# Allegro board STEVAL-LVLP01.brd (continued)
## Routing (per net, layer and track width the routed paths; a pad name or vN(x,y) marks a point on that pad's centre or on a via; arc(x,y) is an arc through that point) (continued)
N470361: length 8.5
  TOP w0.305: U4.4 41.87,75.76 C31.2 41.87,78.86 R81.1 TP14.1
N471408: length 6.7
  TOP w0.305: R76.1 40.07,66.06 41.91,66.06 42.48,66.63 R73.1 42.85,66.45 U2.10
N471412: length 4.7
  TOP w0.305: R75.1 41.27,68.03 R77.1 43.98,67.1 U2.9
N471570: length 4
  TOP w0.305: R74.2 R77.2 44.72,67.75 U2.8
N472042: length 6.6
  TOP w0.305: R81.2 v1(40.45,79.77)
  BOTTOM w0.305: J4.2 37.53,82.69 v1(40.45,79.77)
N472582: length 4.9
  TOP w0.381: R66.1 R57.2 43.31,88.79 41.08,86.57 R58.2
N478538: length 9.1
  TOP w0.305: R101.2 80.39,12.15 80.39,10.11 R96.1 79.63,8.4 J6.1
N478542: length 9.4
  TOP w0.305: R102.2 82.17,12.15 82.17,10.11 R97.1 81.41,9.16 J6.2
N478546: length 10.1
  TOP w0.305: J6.3 83.76,9.35 R98.1 83.95,10.11 83.95,12.15 R104.2
N478738: length 10.5
  TOP w0.508: J5.2 90.04,10.35 90.46,9.93 C42.1 90.46,8.13 90.04,7.72 J6.4
N479415: length 17.1
  TOP w0.254: R106.2 v1(50.45,13)
  BOTTOM w0.254: J9.1 41.34,13.67 49.78,13.67 v1(50.45,13)
N479421: length 13.8
  TOP w0.254: J9.2 43.43,14.11 51.12,14.11 R107.2
N479427: length 10.5
  TOP w0.254: R108.2 52.45,14.56 45.53,14.56 J9.3
N479459: length 32.2
  TOP w0.508: J9.4 46.86,18.65 C48.1 47.41,19.7 47.92,20.21 49.4,20.21 53.85,15.77 65.53,15.77 66.93,17.16 70.87,17.16 J8.2
N479601: length 2.3
  TOP w0.305: R114.2 39.24,5.61
N479607: length 2.3
  TOP w0.305: R115.2 41.78,5.61
N479625: length 2.3
  TOP w0.305: J11.4 R116.2
N479657: length 30.3
  TOP w0.508: J11.5 46.86,8.49 C52.1
  TOP w0.635: J11.5 48.39,4.08 70.74,4.08 J10.2
N479733: length 2.3
  TOP w0.305: R113.2 36.7,5.61
N480096: length 5.5
  TOP w0.381: 34.97,22.71 35.04,22.65 U7.3 ; 34.97,22.71 C51.2 38.71,22.71 R111.2 ; 34.97,22.71 34.97,22.76 R110.1
N487267: length 49.6
  TOP w0.305: v1(96.39,20.46) 102.11,26.18 R28.2 ; R29.1 v1(57.09,21.73)
  BOTTOM w0.305: v1(57.09,21.73) 58.36,20.46 v1(96.39,20.46)
N487934: length 41.9
  TOP w0.305: R30.2 102.11,27.83 v1(96.39,22.12) ; R31.1 v1(65.09,21.73)
  BOTTOM w0.305: v1(96.39,22.12) 95.25,20.97 65.85,20.97 v1(65.09,21.73)
N488373: length 34
  TOP w0.305: R33.1 v1(73.09,21.73) ; R32.2 102.11,29.48 v1(96.39,23.77)
  BOTTOM w0.305: v1(96.39,23.77) 94.23,21.61 73.22,21.61 v1(73.09,21.73)
N490756: length 3.3
  TOP w0.305: C22.2 R45.1 54.93,72.6 R46.1
N494551: length 1.7
  TOP w0.305: 53.34,62.03 53.37,62.06 R72.1
N494643: length 10.4
  TOP w0.305: R68.1 58.86,65.55 57.28,65.55 56.71,64.98 R63.1 55.94,65.55 54.1,65.55 53.53,64.98 R61.2 53.16,65.15 U2.3
N494647: length 7.7
  TOP w0.305: R72.2 R70.2 ; R72.2 R67.1 ; R72.2 54.96,63.48 53.34,63.48 52.32,64.5 U2.2
N494767: length 3.4
  TOP w0.305: R65.1 54.93,58.88 R64.1 C27.2
N495845: length 1.7
  TOP w0.305: R87.1 42.65,62.06 42.67,62.03
N495931: length 10.1
  TOP w0.305: R85.1 37.02,65.55 38.73,65.55 39.31,64.98 R80.1 40.07,65.55 41.91,65.55 42.48,64.98 R78.2 42.85,65.15 U2.12
N495935: length 7.7
  TOP w0.305: R87.2 41.05,63.48 42.67,63.48 43.69,64.5 U2.13 ; R87.2 R84.1 ; R87.2 R89.2
N496035: length 3.3
  TOP w0.305: C32.2 R82.1 41.08,59.01 R83.1
N496697: length 8.5
  TOP w0.381: R51.1 51.94,88.79 50.93,89.81 R50.1 48.58,89.81 R55.2 46.67,89.87 R52.1
N501821: length 90.6
  TOP w0.508: R99.2 94.87,27.64 94.87,4.34 92.71,2.18 R100.1
N513408: length 3.4
  TOP w0.33: C8.1 59.49,35.08 U1.13
N519464: length 2
  TOP w0.508: R105.2 104.84,72.53 LED3.1
N526328: length 1.9
  TOP w0.381: R94.1 36.26,103.52 LED2.2
N526332: length 15.8
  TOP w0.381: LED2.1 44.2,103.52 50.8,96.92 Q7.3
N574651: length 6.4
  TOP w0.305: R108.1 56.07,14.11 57.91,14.11 58.38,13.64 C49.2 58.64,13.23 59.16,12.71 U6.9
N574774: length 6.2
  TOP w0.305: R107.1 56.07,12.34 57.91,12.34 58.38,11.87 C47.2 58.42,11.41 U6.11
N574847: length 6.3
  TOP w0.305: U6.14 58.6,9.46 C46.2 58.38,10.09 57.91,10.56 56.07,10.56 R106.1
N575649: length 30.8
  TOP w0.305: v1(40.01,10.69) 39.43,10.69 R112.2 R114.1 ; U6.3 64.81,9.46 62.61,7.26 54.74,7.26 52.41,9.58 52.41,10.01 v1(52.45,10.05)
  BOTTOM w0.305: v1(52.45,10.05) 52.01,10.49 40.2,10.49 v1(40.01,10.69)
N599590: length 1.4
  TOP w0.508: R34.1 C16.2
N599920: length 1.4
  TOP w0.508: R36.1 C17.2
N600140: length 1.4
  TOP w0.508: R38.1 C18.2
N605072: length 4.6
  TOP w0.381: R66.2 46.29,88.69 U3.4 42.77,86.69 C25.2
N605096: length 6.6
  TOP w0.381: U3.1 46.16,84.79 45.21,85.74 43.69,85.74 43.09,85.14 C25.1 40.92,85.14 R58.1

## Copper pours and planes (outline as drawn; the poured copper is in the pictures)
5V on TOP: 41.02,106.57 41.02,104.79 46.74,104.79 46.74,106.57
5V on TOP: 30.66,18.18 32.84,15.99 32.84,14.75 18.49,14.75 18.36,14.88 18.36,18.05 18.49,18.18 ; 1 cut-out
5V on BOTTOM: 30.81,17.67 31.19,17.29 31.19,15.13 30.81,14.75 18.49,14.75 18.36,14.88 18.36,17.54 18.49,17.67
GND on TOP: 81.15,56.02 81.15,52.98 79.12,52.98 77.72,54.37 77.72,56.02 77.85,56.15 81.03,56.15
GND on TOP: 57.28,87.39 69.34,87.39 69.47,87.27 69.47,82.31 69.85,81.93 104.65,81.93 104.78,81.81 104.78,75.2 104.52,74.95 104.52,73.68 102.87,72.03 102.87,71.14 79.38,71.14 76.45,74.06 70.74,74.06 67.69,71.01 67.69,31.26 70.23,28.72 81.03,28.72 81.15,28.59 81.15,25.16 81.03,25.04 63.75,25.04 63.12,25.67 63.12,29.61 62.36,30.37 61.09,30.37 61.09,31.89 62.36,31.89 63.37,32.91 63.12,79.27 57.15,85.23 57.15,87.27
GND on TOP: 81.15,42.31 81.15,39.26 79.12,39.26 77.72,40.66 77.72,42.31 77.85,42.44 81.03,42.44
GND on TOP: 48.51,44.47 48.51,41.04 51.18,38.37 51.18,36.97 46.74,36.97 46.61,37.1 46.61,44.34 46.74,44.47
GND on BOTTOM: 50.55,36.47 46.48,36.47 46.35,36.59 46.35,52.98 46.48,53.1 56.9,53.1 63.12,59.33 63.12,79.77 58.17,84.73 58.17,87.27 58.42,87.52 69.22,87.52 69.47,87.27 69.47,82.31 69.85,81.93 76.83,81.93 82.04,76.73 82.04,25.16 81.92,25.04 61.98,25.04 ; 2 cut-outs
GND_SIGNAL on TOP: 27.94,101.74 62.36,101.74 62.48,101.62 62.48,98.57 63.25,97.81 63.25,94.89 63.5,94.63 67.69,94.63 67.82,94.51 67.82,93.49 67.69,93.36 66.17,93.36 65.66,93.87 63.5,93.87 63.25,93.62 63.25,88.54 63.37,88.41 63.37,87.65 51.69,87.65 44.7,94.63 40.89,94.63 32.77,86.5 32.77,71.77 26.8,65.8 26.49,65.62 26.46,65.65 26.41,65.66 25.64,65.66 25.55,65.61 25.56,65.5 25.56,65.45 25.53,65.42 24.38,65.42 24.38,64.79 24.24,64.85 24.18,64.99 24.12,65.08 24.01,65.06 23.73,64.78 23.66,64.73 23.58,64.69 23.51,64.62 23.53,64.53 23.59,64.45 23.64,64.36 21.03,64.29 22.04,65.3 22.16,65.38 22.3,65.41 22.41,65.41 22.41,65.48 22.39,65.5 22.24,65.74 22.18,66.03 22.18,66.09 22.19,66.15 22.14,66.26 22.02,66.24 20.1,64.33 20.08,64.3 20.07,64.27 15.49,64.15 15.24,64.41 15.24,89.04 ; 4 cut-outs
GND_SIGNAL on TOP: 39.24,21.73 39.24,19.7 36.45,19.7 35.69,20.46 34.42,20.46 34.42,20.97 35.69,20.97 36.45,21.73
GND_SIGNAL on TOP: 38.61,76.85 38.61,72.66 40.89,72.66 40.89,76.85
GND_SIGNAL on BOTTOM: 13.21,108.35 69.22,108.35 69.47,108.09 69.47,87.9 69.22,87.65 58.29,87.65 58.04,87.39 58.04,84.47 62.99,79.52 62.99,59.33 56.9,53.23 46.48,53.23 46.23,52.98 46.23,36.47 46.35,36.34 49.4,36.34 61.72,24.02 93.98,24.02 94.23,23.77 94.23,1.03 93.98,0.78 13.21,0.78 12.95,1.03 12.95,108.09 ; 8 cut-outs
V1 on TOP (solid shape): 84.38,64.71 85.52,64.71 85.52,62.32 84.38,62.32 84.38,61.74 84.02,61.74 84.02,62.32 83.67,62.32 83.67,64.71 84.02,64.71 84.02,65.3 84.38,65.3
V1 on TOP: 83.82,70.25 83.69,70.12 83.69,58.69 90.17,58.69 96.77,52.09 103.76,52.09 104.01,52.34 104.01,61.61 103.38,62.25 103.38,64.28 102.36,64.28 102.11,64.53 102.11,69.99 101.85,70.25
V2 on TOP (solid shape): 84.38,50.99 85.52,50.99 85.52,48.61 84.38,48.61 84.38,48.02 84.02,48.02 84.02,48.61 83.67,48.61 83.67,50.99 84.02,50.99 84.02,51.58 84.38,51.58
V2 on TOP: 83.69,44.98 103.76,44.98 104.01,45.23 104.01,51.33 103.76,51.58 96.52,51.58 95.5,52.6 83.82,52.6 83.69,52.47
V3 on TOP (solid shape): 84.38,37.28 85.52,37.28 85.52,34.89 84.38,34.89 84.38,34.31 84.02,34.31 84.02,34.89 83.67,34.89 83.67,37.28 84.02,37.28 84.02,37.86 84.38,37.86
V3 on TOP: 83.82,38.88 83.69,38.75 83.69,31.26 103.76,31.26 104.01,31.51 104.01,44.21 103.76,44.47 97.03,44.47 91.44,38.88
VDD on TOP: 36.58,53.48 36.7,53.61 36.7,54.75 36.58,54.88 35.43,54.88 35.43,54.25 36.2,53.48
BUCK_OUT on TOP: 60.2,103.4 60.2,106.7 60.07,106.82 47.12,106.82 46.99,106.7 46.99,103.4 47.12,103.27 60.07,103.27
LSS1 on TOP: 71.95,66.82 71.95,63.52 76.71,63.52 77.22,63.01 83.31,63.01 83.31,66.69 83.19,66.82
LSS3 on TOP: 72.01,39.39 72.01,36.09 76.96,36.09 77.47,35.58 83.31,35.58 83.31,38.75 83.19,38.88 78.87,38.88 78.36,39.39
SHUNT1P on TOP: 71.5,73.55 76.2,73.55 76.45,73.3 76.45,67.07 68.33,67.07 68.33,68.34 71.25,71.26 71.25,73.3
SHUNT2P on TOP: 76.45,39.64 76.45,49.04 76.71,49.29 83.31,49.29 83.31,52.47 83.19,52.6 78.87,52.6 76.45,55.01 76.45,63.26 68.33,63.26 68.33,56.02 69.72,54.63 69.72,53.36 71.25,51.83 71.25,51.33 68.33,48.4 68.33,39.64
SHUNT3P on TOP: 68.33,35.83 76.45,35.83 76.45,29.61 76.2,29.35 71.5,29.35 71.25,29.61 71.25,31.64 68.33,34.56
VM on TOP (solid shape): 85.39,57.98 85.98,57.98 85.98,57.62 85.39,57.62 85.39,56.48 83.01,56.48 83.01,57.62 82.42,57.62 82.42,57.98 83.01,57.98 83.01,58.34 85.39,58.34
VM on TOP (solid shape): 85.39,44.26 85.98,44.26 85.98,43.91 85.39,43.91 85.39,42.77 83.01,42.77 83.01,43.91 82.42,43.91 82.42,44.26 83.01,44.26 83.01,44.62 85.39,44.62
VM on TOP (solid shape): 85.39,30.55 85.98,30.55 85.98,30.19 85.39,30.19 85.39,29.05 83.01,29.05 83.01,30.19 82.42,30.19 82.42,30.55 83.01,30.55 83.01,30.9 85.39,30.9
VM on TOP: 82.55,44.59 82.42,44.47 82.42,39.39 82.55,39.26 91.19,39.26 93.34,41.42 93.34,42.44 91.19,44.59
VM on TOP: 69.85,82.44 69.98,82.31 104.78,82.31 104.78,91.97 104.65,92.09 69.98,92.09 69.85,91.97
VM on TOP: 82.55,58.31 82.42,58.18 82.42,53.1 82.55,52.98 93.09,52.98 93.34,53.23 93.34,55.01 90.04,58.31
VM on TOP: 82.55,30.88 82.42,30.75 82.42,25.67 82.55,25.54 93.09,25.54 93.34,25.8 93.34,30.62 93.09,30.88
VM on BOTTOM: 82.43,24.27 82.3,76.98 76.96,82.31 69.98,82.31 69.85,82.44 69.85,91.97 69.98,92.09 104.65,92.09 104.78,91.97 104.78,82.44 104.65,82.31 100.58,82.31 96.27,78 96.27,25.8 94.74,24.27
N348034 on TOP: 53.85,69.11 52.83,69.11 51.69,67.96 51.69,67.58 50.04,67.58 50.04,70.76 50.8,71.52 53.98,71.52 53.98,69.23
N420950 on TOP: 65.41,96.54 65.53,96.66 68.58,96.66 68.71,96.79 68.71,106.19 68.58,106.32 62.99,106.32 62.87,106.19 62.87,98.32 63.5,97.68 63.5,96.54
N423156 on TOP: 63.5,93.24 63.5,88.92 63.63,88.79 69.47,88.79 69.6,88.92 69.6,92.22 68.58,93.24
N472470 on TOP: 46.35,86.38 46.35,87.14 48.13,88.92 48.9,88.92 48.9,88.28 49.91,87.27 50.67,87.27 50.67,86.25 48.13,86.25 48.01,86.38
N494551 on TOP: 50.04,64.03 51.31,64.03 52.83,62.5 53.85,62.5 53.98,62.37 53.98,60.09 51.18,60.09 50.29,60.98 50.29,62.12 50.04,62.37
N495845 on TOP: 45.97,64.03 45.97,62.37 45.09,61.49 45.09,60.34 44.83,60.09 42.04,60.09 42.04,62.5 43.18,62.5 44.7,64.03

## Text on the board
Ref Des/Silkscreen Top: VBUS | nFAULT | REG12 | VM | CP | OPREF | GND | TPCB | 5V | I3 | I1 | CREF | I2 | PG | PH_1 | CFBK | PH_2 | PH_3 | CURR | REF IN | nSS | A | MISO | B | MOSI | Z | SCLK | SCREF | VEnc | VSPI | 3.3V | H1 | H2 | H3 | VHall | 3sh | 1sh | V1 | V2 | V3 | FOR EVALUATION ONLY | NOT FCC APPROVED FOR RESALE | 6V-45V | STEVAL$LVLP01A | + | - | STEVAL-LVLP01
XSECTION_CHART: *  SURFACE - AIR 0 MIL(+0/-0) | L1 TOP CONDUCTOR - 1OZ_COPPER 1.4 MIL(+0.1/-0.1) | *  DIELECTRIC - FR-4_NO_FLOW_PREPREG 60 MIL(+0/-0) | L2 BOTTOM CONDUCTOR - 1OZ_COPPER 1.4 MIL(+0.1/-0.1) | DESIGN CROSS SECTION CHART | ___________________________ | TOTAL THICKNESS 62.8 MIL | 1-2
PAGE_OUTLINE: 05-July-22 | STEVAL-LVLP01 | STDRIVE101
COMPVAL_TYPE_TOP: 1 : 1 | 1.0 | DRILLING AND PROFILING
User.6: FIGURE | FINISHED_SIZE | 11.81 | 27.56 | 35.43 | 55.0 | 92.52 | 125.98 | DRILL CHART: TOP to BOTTOM | ALL UNITS ARE IN MILS | PLATED | NON-PLATED | QTY | 335 | 164 | 32 | 5 | 2 | 4 | 542 | TOTAL HOLES:
User.9: When THT components aren't mounted yours holes must remain open after solder phase | 1.8 : 1 | 1.0 | ASSEMBLY DRAWING
